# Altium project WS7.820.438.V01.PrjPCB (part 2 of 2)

## Sheet 3-ADC.SchDoc
size A1
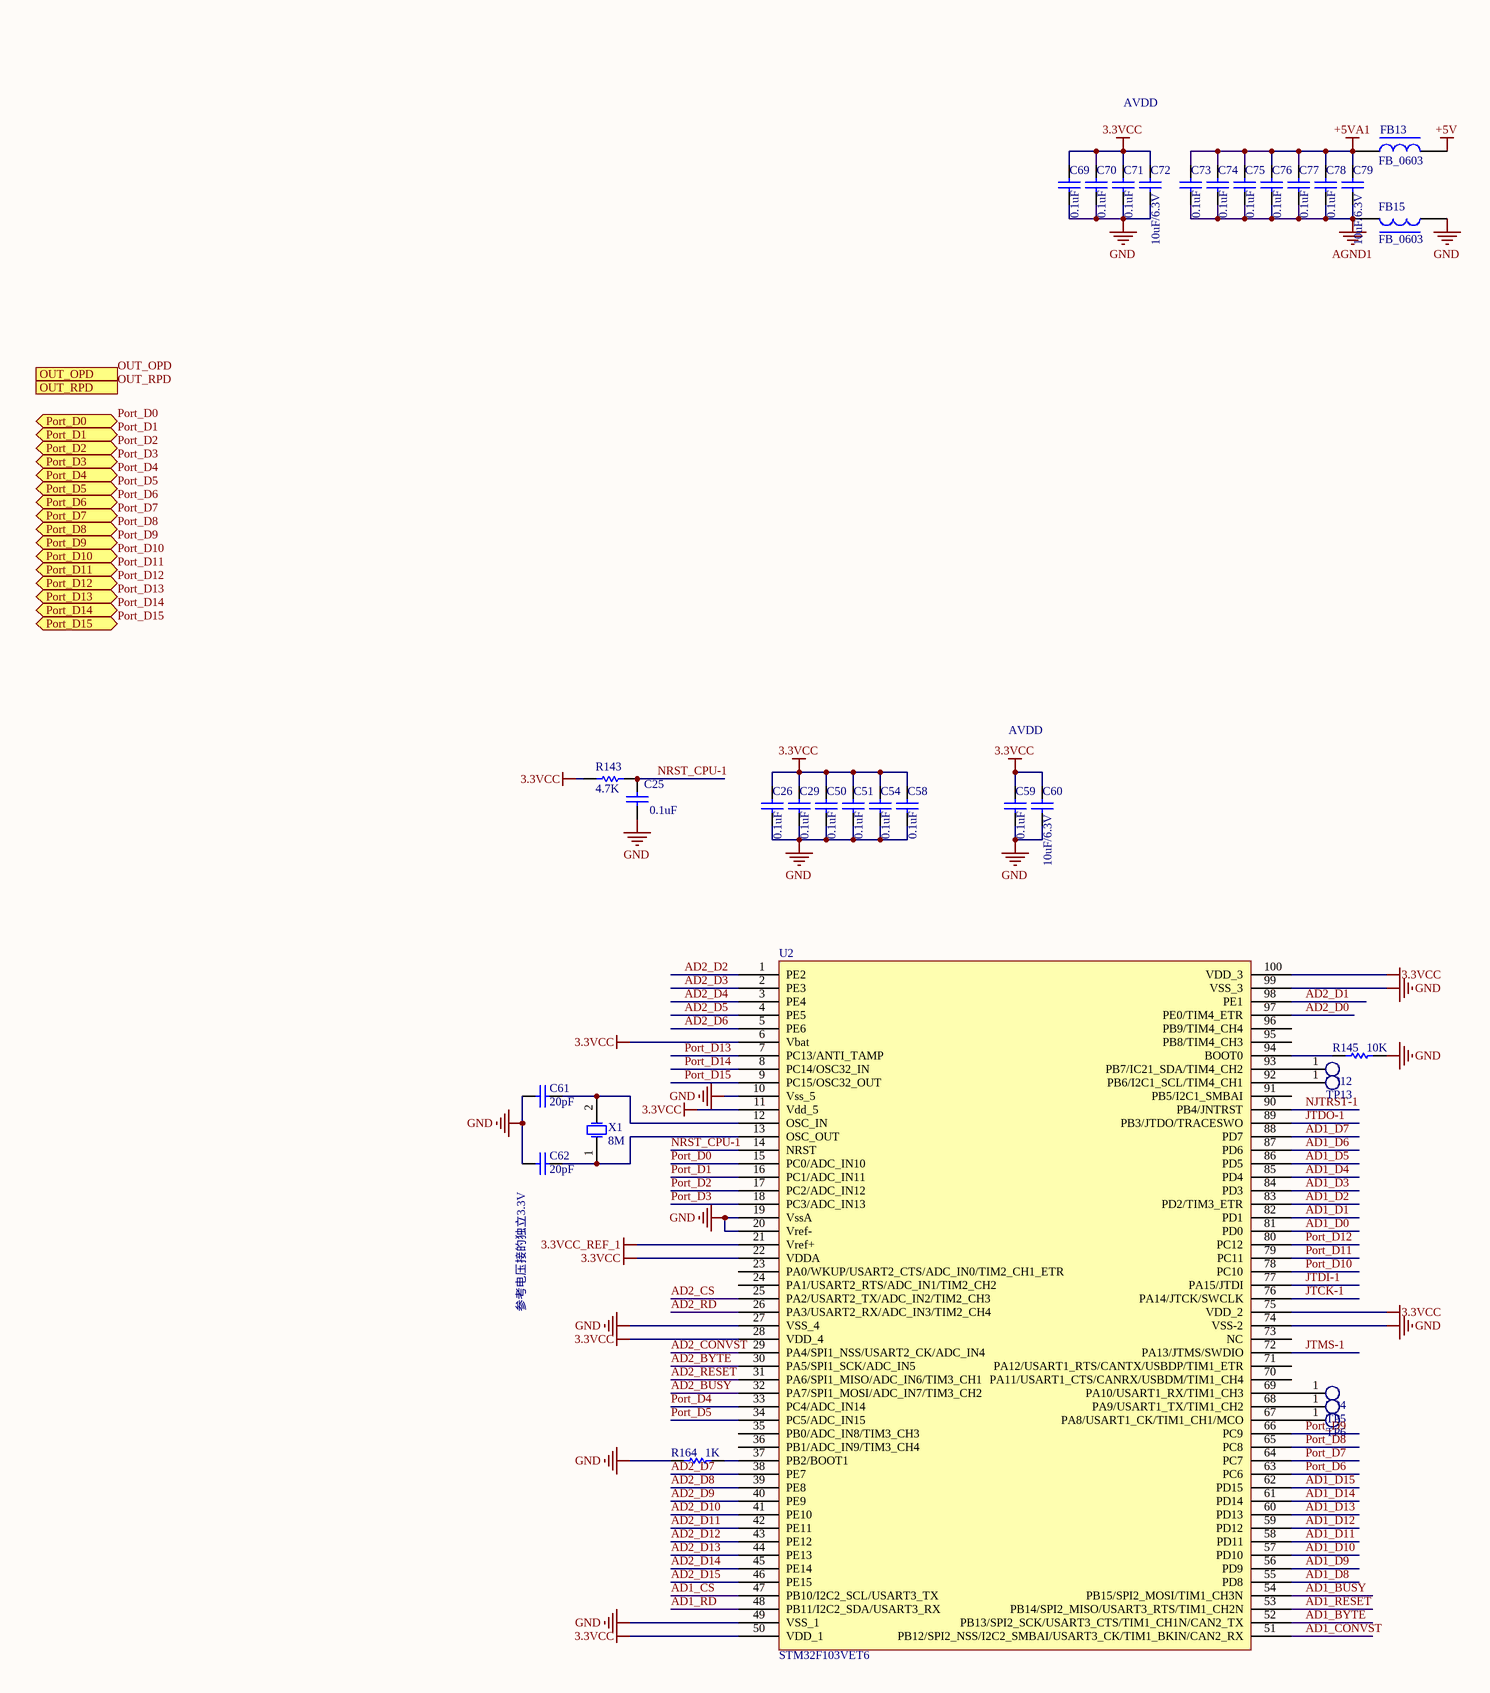
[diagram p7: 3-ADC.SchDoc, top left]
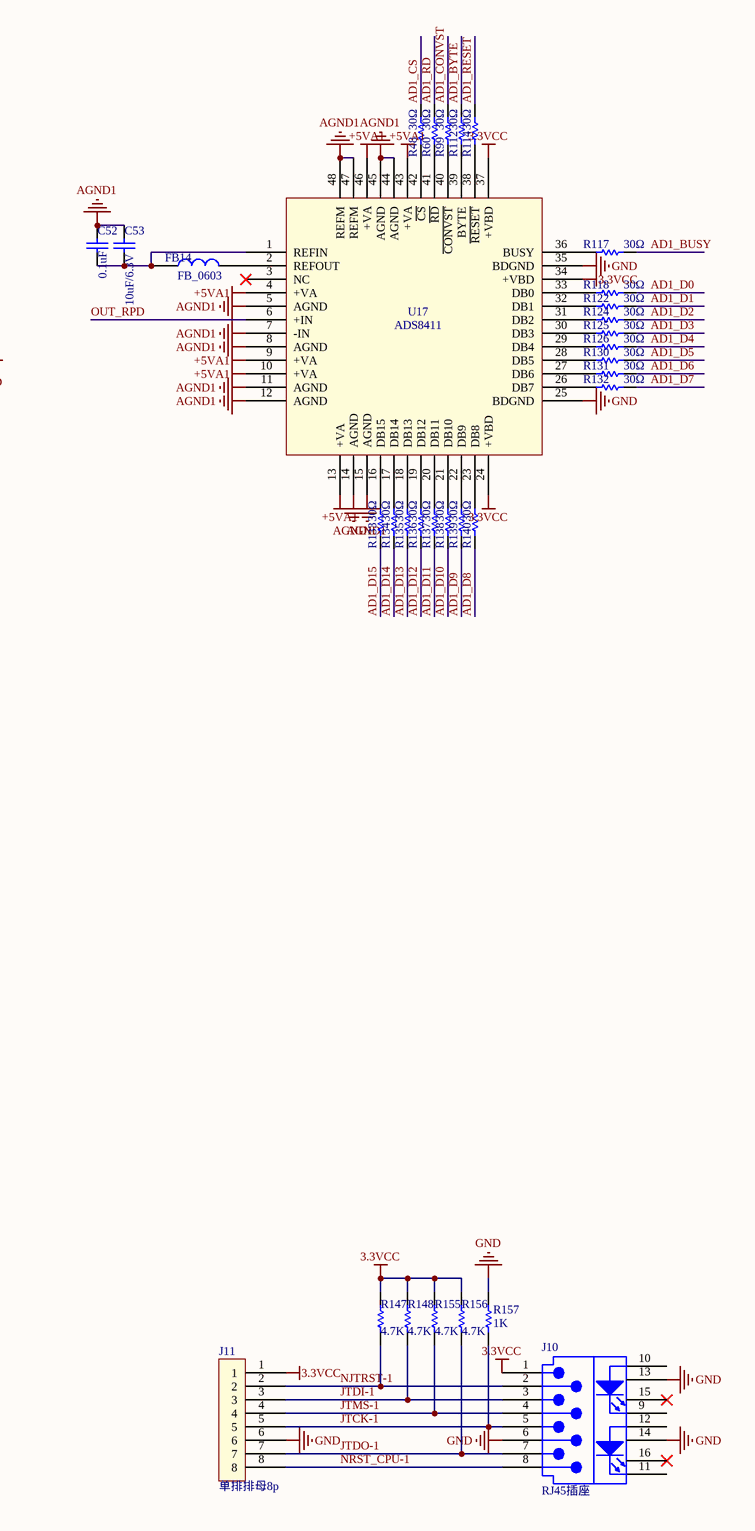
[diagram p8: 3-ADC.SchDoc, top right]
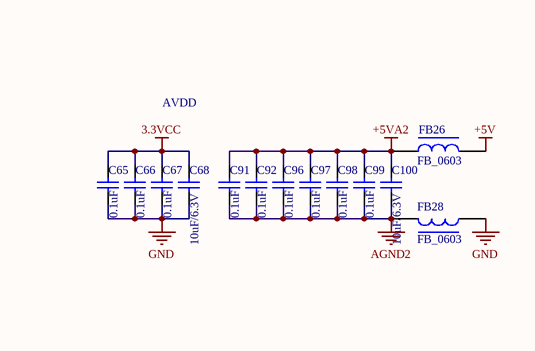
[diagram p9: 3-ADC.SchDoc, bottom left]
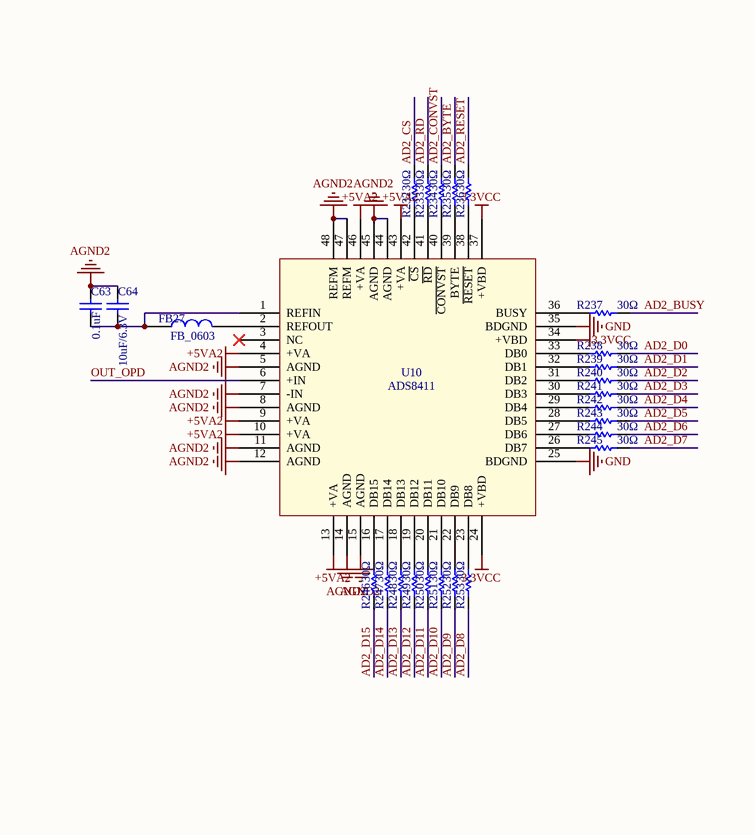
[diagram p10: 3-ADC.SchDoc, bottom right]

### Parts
C25  0.1uF  [C0603]
C26  0.1uF  [C0603]
C29  0.1uF  [C0603]
C50  0.1uF  [C0603]
C51  0.1uF  [C0603]
C52  0.1uF  [C0603]
C53  10uF/6.3V  [C0603]
C54  0.1uF  [C0603]
C58  0.1uF  [C0603]
C59  0.1uF  [C0603]
C60  10uF/6.3V  [C0603]
C61  20pF  [C0603]
C62  20pF  [C0603]
C63  0.1uF  [C0603]
C64  10uF/6.3V  [C0603]
C65  0.1uF  [C0603]
C66  0.1uF  [C0603]
C67  0.1uF  [C0603]
C68  10uF/6.3V  [C0603]
C69  0.1uF  [C0603]
C70  0.1uF  [C0603]
C71  0.1uF  [C0603]
C72  10uF/6.3V  [C0603]
C73  0.1uF  [C0603]
C74  0.1uF  [C0603]
C75  0.1uF  [C0603]
C76  0.1uF  [C0603]
C77  0.1uF  [C0603]
C78  0.1uF  [C0603]
C79  10uF/6.3V  [C0603]
C91  0.1uF  [C0603]
C92  0.1uF  [C0603]
C96  0.1uF  [C0603]
C97  0.1uF  [C0603]
C98  0.1uF  [C0603]
C99  0.1uF  [C0603]
C100  10uF/6.3V  [C0603]
FB13  FB_0603  [L0603]
FB14  FB_0603  [L0603]
FB15  FB_0603  [L0603]
FB26  FB_0603  [L0603]
FB27  FB_0603  [L0603]
FB28  FB_0603  [L0603]
J10  RJ45插座  [RJ45TH-1x1-2R54-LED]
J11  单排排母8p  [SIP8TM-2R54]
R48  30Ω  [R0603]
R60  30Ω  [R0603]
R99  30Ω  [R0603]
R112  30Ω  [R0603]
R114  30Ω  [R0603]
R117  30Ω  [R0603]
R118  30Ω  [R0603]
R122  30Ω  [R0603]
R124  30Ω  [R0603]
R125  30Ω  [R0603]
R126  30Ω  [R0603]
R130  30Ω  [R0603]
R131  30Ω  [R0603]
R132  30Ω  [R0603]
R133  30Ω  [R0603]
R134  30Ω  [R0603]
R135  30Ω  [R0603]
R136  30Ω  [R0603]
R137  30Ω  [R0603]
R138  30Ω  [R0603]
R139  30Ω  [R0603]
R140  30Ω  [R0603]
R143  4.7K  [R0603]
R145  10K  [R0603]
R147  4.7K  [R0603]
R148  4.7K  [R0603]
R155  4.7K  [R0603]
R156  4.7K  [R0603]
R157  1K  [R0603]
R164  1K  [R0603]
R232  30Ω  [R0603]
R233  30Ω  [R0603]
R234  30Ω  [R0603]
R235  30Ω  [R0603]
R236  30Ω  [R0603]
R237  30Ω  [R0603]
R238  30Ω  [R0603]
R239  30Ω  [R0603]
R240  30Ω  [R0603]
R241  30Ω  [R0603]
R242  30Ω  [R0603]
R243  30Ω  [R0603]
R244  30Ω  [R0603]
R245  30Ω  [R0603]
R246  30Ω  [R0603]
R247  30Ω  [R0603]
R248  30Ω  [R0603]
R249  30Ω  [R0603]
R250  30Ω  [R0603]
R251  30Ω  [R0603]
R252  30Ω  [R0603]
R253  30Ω  [R0603]
TP4  TEST  [TP0R8]  (value not drawn)  (no BOM)
TP5  TEST  [TP0R8]  (value not drawn)  (no BOM)
TP6  TEST  [TP0R8]  (value not drawn)  (no BOM)
TP12  TEST  [TP0R8]  (value not drawn)  (no BOM)
TP13  TEST  [TP0R8]  (value not drawn)  (no BOM)
U2  STM32F103VET6  [LQFP100_0R5_14x14]
U10  ADS8411  [TQFN48-0R5-7X7]
U17  ADS8411  [TQFN48-0R5-7X7]
X1  8M  [CRY2SM-6R0x3R5]

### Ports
OUT_OPD (in), OUT_RPD (in), Port_D0 (bidir), Port_D1 (bidir), Port_D2 (bidir), Port_D3 (bidir), Port_D4 (bidir), Port_D5 (bidir), Port_D6 (bidir), Port_D7 (bidir), Port_D8 (bidir), Port_D9 (bidir), Port_D10 (bidir), Port_D11 (bidir), Port_D12 (bidir), Port_D13 (bidir), Port_D14 (bidir), Port_D15 (bidir)

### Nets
3.3VCC: C26.2 C29.2 C50.2 C51.2 C54.2 C58.2 C59.2 C60.2 C65.2 C66.2 C67.2 C68.2 C69.2 C70.2 C71.2 C72.2 J10.1(TX+) J11.1 R143.2 R147.2 R148.2 R155.2 R156.2 U2.6(Vbat) U2.11(Vdd_5) U2.22(VDDA) U2.28(VDD_4) U2.50(VDD_1) U2.75(VDD_2) U2.100(VDD_3) U10.24(+VBD) U10.34(+VBD) U10.37(+VBD) U17.24(+VBD) U17.34(+VBD) U17.37(+VBD)
3.3VCC_REF_1: U2.21(Vref+)
+5V: FB13.2 FB26.2
+5VA1: C73.2 C74.2 C75.2 C76.2 C77.2 C78.2 C79.2 FB13.1 U17.4(+VA) U17.9(+VA) U17.10(+VA) U17.13(+VA) U17.43(+VA) U17.46(+VA)
+5VA2: C91.2 C92.2 C96.2 C97.2 C98.2 C99.2 C100.2 FB26.1 U10.4(+VA) U10.9(+VA) U10.10(+VA) U10.13(+VA) U10.43(+VA) U10.46(+VA)
AGND1: C52.2 C53.2 C73.1 C74.1 C75.1 C76.1 C77.1 C78.1 C79.1 FB15.2 U17.5(AGND) U17.7(-IN) U17.8(AGND) U17.11(AGND) U17.12(AGND) U17.14(AGND) U17.15(AGND) U17.44(AGND) U17.45(AGND) U17.47(REFM) U17.48(REFM)
AGND2: C63.2 C64.2 C91.1 C92.1 C96.1 C97.1 C98.1 C99.1 C100.1 FB28.2 U10.5(AGND) U10.7(-IN) U10.8(AGND) U10.11(AGND) U10.12(AGND) U10.14(AGND) U10.15(AGND) U10.44(AGND) U10.45(AGND) U10.47(REFM) U10.48(REFM)
GND: C25.1 C26.1 C29.1 C50.1 C51.1 C54.1 C58.1 C59.1 C60.1 C61.2 C62.2 C65.1 C66.1 C67.1 C68.1 C69.1 C70.1 C71.1 C72.1 FB15.1 FB28.1 J10.6(RX-) J10.13 J10.14 J11.6 R145.1 R157.1 R164.1 U2.10(Vss_5) U2.19(VssA) U2.20(Vref-) U2.27(VSS_4) U2.49(VSS_1) U2.74(VSS-2) U2.99(VSS_3) U10.25(BDGND) U10.35(BDGND) U17.25(BDGND) U17.35(BDGND)
AD1_BUSY: R117.2 U2.54(PB15/SPI2_MOSI/TIM1_CH3N)
AD1_BYTE: R112.2 U2.52(PB13/SPI2_SCK/USART3_CTS/TIM1_CH1N/CAN2_TX)
AD1_CONVST: R99.2 U2.51(PB12/SPI2_NSS/I2C2_SMBAI/USART3_CK/TIM1_BKIN/CAN2_RX)
AD1_CS: R48.2 U2.47(PB10/I2C2_SCL/USART3_TX)
AD1_D0: R118.2 U2.81(PD0)
AD1_D1: R122.2 U2.82(PD1)
AD1_D2: R124.2 U2.83(PD2/TIM3_ETR)
AD1_D3: R125.2 U2.84(PD3)
AD1_D4: R126.2 U2.85(PD4)
AD1_D5: R130.2 U2.86(PD5)
AD1_D6: R131.2 U2.87(PD6)
AD1_D7: R132.2 U2.88(PD7)
AD1_D8: R140.1 U2.55(PD8)
AD1_D9: R139.1 U2.56(PD9)
AD1_D10: R138.1 U2.57(PD10)
AD1_D11: R137.1 U2.58(PD11)
AD1_D12: R136.1 U2.59(PD12)
AD1_D13: R135.1 U2.60(PD13)
AD1_D14: R134.1 U2.61(PD14)
AD1_D15: R133.1 U2.62(PD15)
AD1_RD: R60.2 U2.48(PB11/I2C2_SDA/USART3_RX)
AD1_RESET: R114.2 U2.53(PB14/SPI2_MISO/USART3_RTS/TIM1_CH2N)
AD2_BUSY: R237.2 U2.32(PA7/SPI1_MOSI/ADC_IN7/TIM3_CH2)
AD2_BYTE: R235.2 U2.30(PA5/SPI1_SCK/ADC_IN5)
AD2_CONVST: R234.2 U2.29(PA4/SPI1_NSS/USART2_CK/ADC_IN4)
AD2_CS: R232.2 U2.25(PA2/USART2_TX/ADC_IN2/TIM2_CH3)
AD2_D0: R238.2 U2.97(PE0/TIM4_ETR)
AD2_D1: R239.2 U2.98(PE1)
AD2_D2: R240.2 U2.1(PE2)
AD2_D3: R241.2 U2.2(PE3)
AD2_D4: R242.2 U2.3(PE4)
AD2_D5: R243.2 U2.4(PE5)
AD2_D6: R244.2 U2.5(PE6)
AD2_D7: R245.2 U2.38(PE7)
AD2_D8: R253.1 U2.39(PE8)
AD2_D9: R252.1 U2.40(PE9)
AD2_D10: R251.1 U2.41(PE10)
AD2_D11: R250.1 U2.42(PE11)
AD2_D12: R249.1 U2.43(PE12)
AD2_D13: R248.1 U2.44(PE13)
AD2_D14: R247.1 U2.45(PE14)
AD2_D15: R246.1 U2.46(PE15)
AD2_RD: R233.2 U2.26(PA3/USART2_RX/ADC_IN3/TIM2_CH4)
AD2_RESET: R236.2 U2.31(PA6/SPI1_MISO/ADC_IN6/TIM3_CH1)
JTCK-1: J10.5(NC) J11.5 R157.2 U2.76(PA14/JTCK/SWCLK)
JTDI-1: J10.3(RX+) J11.3 R148.1 U2.77(PA15/JTDI)
JTDO-1: J10.7(NC) J11.7 R156.1 U2.89(PB3/JTDO/TRACESWO)
JTMS-1: J10.4(NC) J11.4 R155.1 U2.72(PA13/JTMS/SWDIO)
NJTRST-1: J10.2(TX-) J11.2 R147.1 U2.90(PB4/JNTRST)
NRST_CPU-1: C25.2 J10.8(NC) J11.8 R143.1 U2.14(NRST)
OUT_OPD: U10.6(+IN) ; port OUT_OPD
OUT_RPD: U17.6(+IN) ; port OUT_RPD
Port_D0: U2.15(PC0/ADC_IN10) ; port Port_D0
Port_D1: U2.16(PC1/ADC_IN11) ; port Port_D1
Port_D2: U2.17(PC2/ADC_IN12) ; port Port_D2
Port_D3: U2.18(PC3/ADC_IN13) ; port Port_D3
Port_D4: U2.33(PC4/ADC_IN14) ; port Port_D4
Port_D5: U2.34(PC5/ADC_IN15) ; port Port_D5
Port_D6: U2.63(PC6) ; port Port_D6
Port_D7: U2.64(PC7) ; port Port_D7
Port_D8: U2.65(PC8) ; port Port_D8
Port_D9: U2.66(PC9) ; port Port_D9
Port_D10: U2.78(PC10) ; port Port_D10
Port_D11: U2.79(PC11) ; port Port_D11
Port_D12: U2.80(PC12) ; port Port_D12
Port_D13: U2.7(PC13/ANTI_TAMP) ; port Port_D13
Port_D14: U2.8(PC14/OSC32_IN) ; port Port_D14
Port_D15: U2.9(PC15/OSC32_OUT) ; port Port_D15
NetC52_1: C52.1 C53.1 FB14.1 U17.1(REFIN)
NetC61_1: C61.1 U2.12(OSC_IN) X1.2(OSC2)
NetC62_1: C62.1 U2.13(OSC_OUT) X1.1(OSC1)
NetC63_1: C63.1 C64.1 FB27.1 U10.1(REFIN)
NetFB14_2: FB14.2 U17.2(REFOUT)
NetFB27_2: FB27.2 U10.2(REFOUT)
NetR48_1: R48.1 U17.42(~{CS})
NetR60_1: R60.1 U17.41(~{RD})
NetR99_1: R99.1 U17.40(~{CONVST})
NetR112_1: R112.1 U17.39(BYTE)
NetR114_1: R114.1 U17.38(~{RESET})
NetR117_1: R117.1 U17.36(BUSY)
NetR118_1: R118.1 U17.33(DB0)
NetR122_1: R122.1 U17.32(DB1)
NetR124_1: R124.1 U17.31(DB2)
NetR125_1: R125.1 U17.30(DB3)
NetR126_1: R126.1 U17.29(DB4)
NetR130_1: R130.1 U17.28(DB5)
NetR131_1: R131.1 U17.27(DB6)
NetR132_1: R132.1 U17.26(DB7)
NetR133_2: R133.2 U17.16(DB15)
NetR134_2: R134.2 U17.17(DB14)
NetR135_2: R135.2 U17.18(DB13)
NetR136_2: R136.2 U17.19(DB12)
NetR137_2: R137.2 U17.20(DB11)
NetR138_2: R138.2 U17.21(DB10)
NetR139_2: R139.2 U17.22(DB9)
NetR140_2: R140.2 U17.23(DB8)
NetR145_2: R145.2 U2.94(BOOT0)
NetR164_2: R164.2 U2.37(PB2/BOOT1)
NetR232_1: R232.1 U10.42(~{CS})
NetR233_1: R233.1 U10.41(~{RD})
NetR234_1: R234.1 U10.40(~{CONVST})
NetR235_1: R235.1 U10.39(BYTE)
NetR236_1: R236.1 U10.38(~{RESET})
NetR237_1: R237.1 U10.36(BUSY)
NetR238_1: R238.1 U10.33(DB0)
NetR239_1: R239.1 U10.32(DB1)
NetR240_1: R240.1 U10.31(DB2)
NetR241_1: R241.1 U10.30(DB3)
NetR242_1: R242.1 U10.29(DB4)
NetR243_1: R243.1 U10.28(DB5)
NetR244_1: R244.1 U10.27(DB6)
NetR245_1: R245.1 U10.26(DB7)
NetR246_2: R246.2 U10.16(DB15)
NetR247_2: R247.2 U10.17(DB14)
NetR248_2: R248.2 U10.18(DB13)
NetR249_2: R249.2 U10.19(DB12)
NetR250_2: R250.2 U10.20(DB11)
NetR251_2: R251.2 U10.21(DB10)
NetR252_2: R252.2 U10.22(DB9)
NetR253_2: R253.2 U10.23(DB8)
NetTP4_1: TP4.1(TP) U2.69(PA10/USART1_RX/TIM1_CH3)
NetTP5_1: TP5.1(TP) U2.68(PA9/USART1_TX/TIM1_CH2)
NetTP6_1: TP6.1(TP) U2.67(PA8/USART1_CK/TIM1_CH1/MCO)
NetTP12_1: TP12.1(TP) U2.93(PB7/IC21_SDA/TIM4_CH2)
NetTP13_1: TP13.1(TP) U2.92(PB6/I2C1_SCL/TIM4_CH1)

Not connected (* = marked no-connect by the designer): J10 9(K1) 10(A1) 11(K2) 12(A2) 15* 16*; U2 23(PA0/WKUP/USART2_CTS/ADC_IN0/TIM2_CH1_ETR) 24(PA1/USART2_RTS/ADC_IN1/TIM2_CH2) 35(PB0/ADC_IN8/TIM3_CH3) 36(PB1/ADC_IN9/TIM3_CH4) 70(PA11/USART1_CTS/CANRX/USBDM/TIM1_CH4) 71(PA12/USART1_RTS/CANTX/USBDP/TIM1_ETR) 73(NC) 91(PB5/I2C1_SMBAI) 95(PB8/TIM4_CH3) 96(PB9/TIM4_CH4); U10 3(NC)*; U17 3(NC)*

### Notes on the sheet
- AVDD
- 参考电压接的独立3.3V

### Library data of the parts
C25 C26 C29 C50-C52 C54 C58 C59 C63 C65-C67 C69-C71 C73-C78 C91 C92 C96-C99 = 0.1uF贴片电容: 贴片电容_GRM188R71H104KA01D_0.1uF±10%,50V,0603; code: 01010045
C53 C60 C64 C68 C72 C79 C100 = 10uF贴片电容: 贴片电容_GRM188R60J106ME47D_10uF±20%,6.3V,0603; code: 01010037
C61 C62 = 20pF贴片电容: 贴片电容_GRM188C1H200JB01D_20pF±5%,50V,0603; code: 01010035
FB13-FB15 FB26-FB28 = 0603贴片磁珠: 贴片磁珠_100R,0603; code: 0103016
J10 = RJ45弯脚带灯: RJ45插座_1*1,带左黄右绿灯,弯脚; MPN: 朱迅; code: 01090042
J11 = 8p-2.54单排母座: 连接器_单排排母座8p_直插,间距2.54mm; MPN: WS; code: 01090052
R48 R60 R99 R112 R114 R117 R118 R122 R124-R126 R130-R140 R232-R253 = 30Ω贴片电阻: 贴片电阻_30Ω±5%,0603; code: 01020108
R143 R147 R148 R155 R156 = 4.7K贴片电阻: 贴片电阻_4.7K±5%,0603; code: 01020012
R145 = 10K贴片电阻: 贴片电阻_10K±5%,0603; code: 01020011
R157 R164 = 1K贴片电阻: 贴片电阻_1K±5%,0603; code: 01020082
TP4-TP6 TP12 TP13 = TP0.8mm: 表贴测试点0.8mm
U2 = STM32F103VET: MCU_STM32F103VET6_32 bit, LQFP100; Maker: ST; code: 01060037
U10 U17 = ADS8411: 模数转换芯片_ADS8411_16-Bit,2MSPS,QFN48
X1 = 8M贴片无源晶体: 贴片无源晶体_8MHz,封装6035; code: 03050006

## Sheet 4-RF-PD.SchDoc
size A2
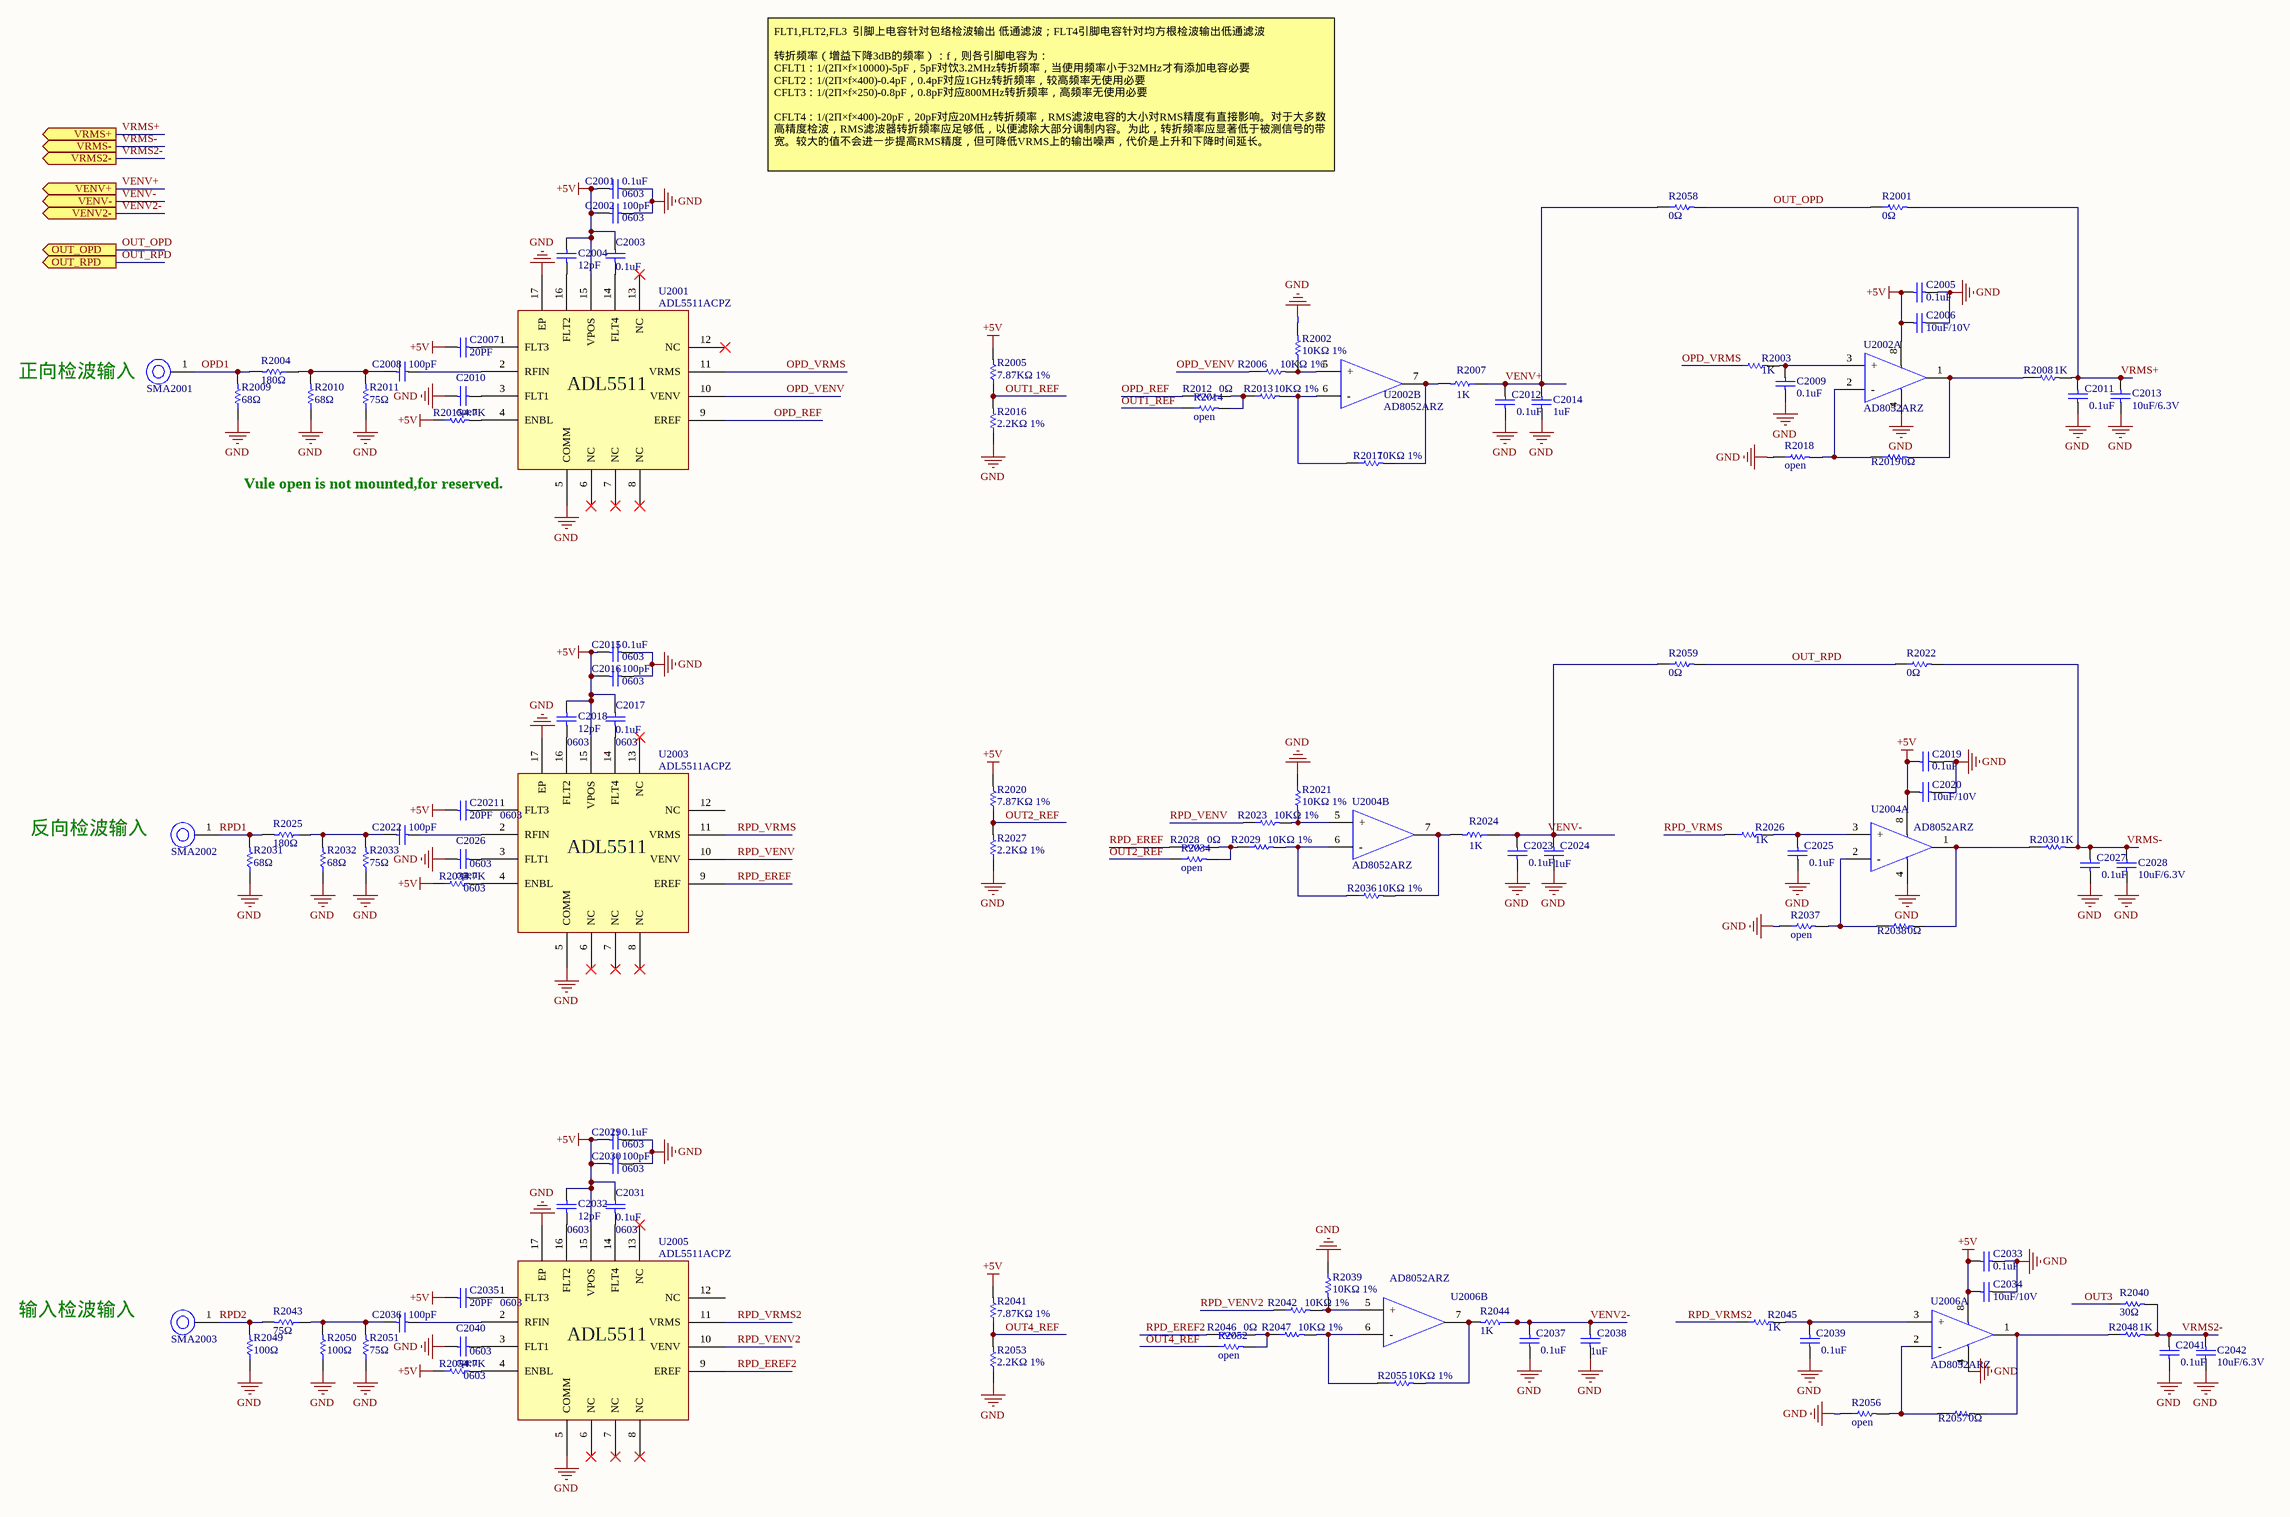
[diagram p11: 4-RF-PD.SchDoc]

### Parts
C2001  0.1uF  [C0603]
C2002  100pF  [C0603]
C2003  0.1uF  [C0603]
C2004  12pF  [C0603]
C2005  0.1uF  [C0603]
C2006  10uF/10V  [C0805]
C2007  20PF  [C0603]
C2008  100pF  [C0805]
C2009  0.1uF  [C0603]
C2010  open  [C0603]  (no BOM)
C2011  0.1uF  [C0603]
C2012  0.1uF  [C0603]
C2013  10uF/6.3V  [C0603]
C2014  1uF  [C0603]
C2015  0.1uF  [C0603]
C2016  100pF  [C0603]
C2017  0.1uF  [C0603]
C2018  12pF  [C0603]
C2019  0.1uF  [C0603]
C2020  10uF/10V  [C0805]
C2021  20PF  [C0603]
C2022  100pF  [C0805]
C2023  0.1uF  [C0603]
C2024  1uF  [C0603]
C2025  0.1uF  [C0603]
C2026  open  [C0603]  (no BOM)
C2027  0.1uF  [C0603]
C2028  10uF/6.3V  [C0603]
C2029  0.1uF  [C0603]
C2030  100pF  [C0603]
C2031  0.1uF  [C0603]
C2032  12pF  [C0603]
C2033  0.1uF  [C0603]
C2034  10uF/10V  [C0805]
C2035  20PF  [C0603]
C2036  100pF  [C0805]
C2037  0.1uF  [C0603]
C2038  1uF  [C0603]
C2039  0.1uF  [C0603]
C2040  open  [C0603]  (no BOM)
C2041  0.1uF  [C0603]
C2042  10uF/6.3V  [C0603]
R2001  0Ω  [R0603]  (no BOM)
R2002  10KΩ 1%  [R0603]
R2003  1K  [R0603]
R2004  180Ω  [R1206]
R2005  7.87KΩ 1%  [R0603]
R2006  10KΩ 1%  [R0603]
R2007  1K  [R0603]
R2008  1K  [R0603]
R2009  68Ω  [R1206]
R2010  68Ω  [R1206]
R2011  75Ω  [R0805]
R2012  0Ω  [R0603]
R2013  10KΩ 1%  [R0603]
R2014  open  [R0603]  (no BOM)
R2015  4.7K  [R0603]
R2016  2.2KΩ 1%  [R0603]
R2017  10KΩ 1%  [R0603]
R2018  open  [R0603]  (no BOM)
R2019  0Ω  [R0603]
R2020  7.87KΩ 1%  [R0603]
R2021  10KΩ 1%  [R0603]
R2022  0Ω  [R0603]  (no BOM)
R2023  10KΩ 1%  [R0603]
R2024  1K  [R0603]
R2025  180Ω  [R1206]
R2026  1K  [R0603]
R2027  2.2KΩ 1%  [R0603]
R2028  0Ω  [R0603]
R2029  10KΩ 1%  [R0603]
R2030  1K  [R0603]
R2031  68Ω  [R1206]
R2032  68Ω  [R1206]
R2033  75Ω  [R0805]
R2034  open  [R0603]  (no BOM)
R2035  4.7K  [R0603]
R2036  10KΩ 1%  [R0603]
R2037  open  [R0603]  (no BOM)
R2038  0Ω  [R0603]
R2039  10KΩ 1%  [R0603]
R2040  30Ω  [R0603]
R2041  7.87KΩ 1%  [R0603]
R2042  10KΩ 1%  [R0603]
R2043  75Ω  [R1206]
R2044  1K  [R0603]
R2045  1K  [R0603]
R2046  0Ω  [R0603]
R2047  10KΩ 1%  [R0603]
R2048  1K  [R0603]
R2049  100Ω  [R1206]
R2050  100Ω  [R1206]
R2051  75Ω  [R0805]
R2052  open  [R0603]  (no BOM)
R2053  2.2KΩ 1%  [R0603]
R2054  4.7K  [R0603]
R2055  10KΩ 1%  [R0603]
R2056  open  [R0603]  (no BOM)
R2057  0Ω  [R0603]
R2058  0Ω  [R0603]
R2059  0Ω  [R0603]
SMA2001  SMA-50KFD-4  [SMA-50KFD-4]  (value not drawn)  (no BOM)
SMA2002  SMA-50KFD-4  [SMA-50KFD-4]  (value not drawn)  (no BOM)
SMA2003  SMA-50KFD-4  [SMA-50KFD-4]  (value not drawn)  (no BOM)
U2001  ADL5511ACPZ  [QFN16_0R50_3X3]
U2002  AD8052ARZ  [SOIC8_1R27_3R9x4R9]  (parts A,B of 2)
U2003  ADL5511ACPZ  [QFN16_0R50_3X3]
U2004  AD8052ARZ  [SOIC8_1R27_3R9x4R9]  (parts A,B of 2)
U2005  ADL5511ACPZ  [QFN16_0R50_3X3]
U2006  AD8052ARZ  [SOIC8_1R27_3R9x4R9]  (parts A,B of 2)

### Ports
OUT_OPD (out), OUT_RPD (out), VENV2- (out), VENV+ (out), VENV- (out), VRMS2- (out), VRMS+ (out), VRMS- (out)

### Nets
+5V: C2001.2 C2002.1 C2003.2 C2004.2 C2005.1 C2006.1 C2007.1 C2015.2 C2016.1 C2017.2 C2018.2 C2019.1 C2020.1 C2021.1 C2029.2 C2030.1 C2031.2 C2032.2 C2033.1 C2034.1 C2035.1 R2005.2 R2015.1 R2020.2 R2035.1 R2041.2 R2054.1 U2001.15(VPOS) U2002.8 U2003.15(VPOS) U2004.8 U2005.15(VPOS) U2006.8
GND: C2001.1 C2002.2 C2005.2 C2006.2 C2009.1 C2010.1 C2011.1 C2012.1 C2013.1 C2014.1 C2015.1 C2016.2 C2019.2 C2020.2 C2023.1 C2024.1 C2025.1 C2026.1 C2027.1 C2028.1 C2029.1 C2030.2 C2033.2 C2034.2 C2037.1 C2038.1 C2039.1 C2040.1 C2041.1 C2042.1 R2002.2 R2009.1 R2010.1 R2011.1 R2016.1 R2018.1 R2021.1 R2027.1 R2031.1 R2032.1 R2033.1 R2037.1 R2039.1 R2049.1 R2050.1 R2051.1 R2053.1 R2056.1 U2001.5(COMM) U2001.17(EP) U2002.4 U2003.5(COMM) U2003.17(EP) U2004.4 U2005.5(COMM) U2005.17(EP) U2006.4
OPD1: R2004.2 R2009.2 SMA2001.1(Sig)
OPD_REF: R2012.1 U2001.9(EREF)
OPD_VENV: R2006.1 U2001.10(VENV)
OPD_VRMS: R2003.1 U2001.11(VRMS)
OUT1_REF: R2005.1 R2014.1 R2016.2
OUT2_REF: R2020.1 R2027.2 R2034.1
OUT3: R2040.1
OUT4_REF: R2041.1 R2052.1 R2053.2
OUT_OPD: R2001.1 R2058.2 ; port OUT_OPD
OUT_RPD: R2022.1 R2059.2 ; port OUT_RPD
RPD1: R2025.2 R2031.2 SMA2002.1(Sig)
RPD2: R2043.2 R2049.2 SMA2003.1(Sig)
RPD_EREF: R2028.1 U2003.9(EREF)
RPD_EREF2: R2046.1 U2005.9(EREF)
RPD_VENV: R2023.1 U2003.10(VENV)
RPD_VENV2: R2042.1 U2005.10(VENV)
RPD_VRMS: R2026.1 U2003.11(VRMS)
RPD_VRMS2: R2045.1 U2005.11(VRMS)
VENV2-: C2037.2 C2038.2 R2044.1 ; port VENV2-
VENV+: C2012.2 C2014.2 R2007.1 R2058.1 ; port VENV+
VENV-: C2023.2 C2024.2 R2024.1 R2059.1 ; port VENV-
VRMS2-: C2041.2 C2042.2 R2040.2 R2048.2 ; port VRMS2-
VRMS+: C2011.2 C2013.2 R2001.2 R2008.2 ; port VRMS+
VRMS-: C2027.2 C2028.2 R2022.2 R2030.2 ; port VRMS-
NetC2003_1: C2003.1 U2001.14(FLT4)
NetC2004_1: C2004.1 U2001.16(FLT2)
NetC2007_2: C2007.2 U2001.1(FLT3)
NetC2008_1: C2008.1 R2004.1 R2010.2 R2011.2
NetC2008_2: C2008.2 U2001.2(RFIN)
NetC2009_2: C2009.2 R2003.2 U2002.3(+)
NetC2010_2: C2010.2 U2001.3(FLT1)
NetC2017_1: C2017.1 U2003.14(FLT4)
NetC2018_1: C2018.1 U2003.16(FLT2)
NetC2021_2: C2021.2 U2003.1(FLT3)
NetC2022_1: C2022.1 R2025.1 R2032.2 R2033.2
NetC2022_2: C2022.2 U2003.2(RFIN)
NetC2025_2: C2025.2 R2026.2 U2004.3(+)
NetC2026_2: C2026.2 U2003.3(FLT1)
NetC2031_1: C2031.1 U2005.14(FLT4)
NetC2032_1: C2032.1 U2005.16(FLT2)
NetC2035_2: C2035.2 U2005.1(FLT3)
NetC2036_1: C2036.1 R2043.1 R2050.2 R2051.2
NetC2036_2: C2036.2 U2005.2(RFIN)
NetC2039_2: C2039.2 R2045.2 U2006.3(+)
NetC2040_2: C2040.2 U2005.3(FLT1)
NetR2002_1: R2002.1 R2006.2 U2002.5(+)
NetR2007_2: R2007.2 R2017.2 U2002.7
NetR2008_1: R2008.1 R2019.2 U2002.1
NetR2012_2: R2012.2 R2013.1 R2014.2
NetR2013_2: R2013.2 R2017.1 U2002.6(-)
NetR2015_2: R2015.2 U2001.4(ENBL)
NetR2018_2: R2018.2 R2019.1 U2002.2(-)
NetR2021_2: R2021.2 R2023.2 U2004.5(+)
NetR2024_2: R2024.2 R2036.2 U2004.7
NetR2028_2: R2028.2 R2029.1 R2034.2
NetR2029_2: R2029.2 R2036.1 U2004.6(-)
NetR2030_1: R2030.1 R2038.2 U2004.1
NetR2035_2: R2035.2 U2003.4(ENBL)
NetR2037_2: R2037.2 R2038.1 U2004.2(-)
NetR2039_2: R2039.2 R2042.2 U2006.5(+)
NetR2044_2: R2044.2 R2055.2 U2006.7
NetR2046_2: R2046.2 R2047.1 R2052.2
NetR2047_2: R2047.2 R2055.1 U2006.6(-)
NetR2048_1: R2048.1 R2057.2 U2006.1
NetR2054_2: R2054.2 U2005.4(ENBL)
NetR2056_2: R2056.2 R2057.1 U2006.2(-)

Not connected (* = marked no-connect by the designer): U2001 6(NC)* 7(NC)* 8(NC)* 12(NC)* 13(NC)*; U2003 6(NC)* 7(NC)* 8(NC)* 12(NC) 13(NC)*; U2005 6(NC)* 7(NC)* 8(NC)* 12(NC) 13(NC)*

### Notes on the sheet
- FLT1,FLT2,FL3  引脚上电容针对包络检波输出 低通滤波；FLT4引脚电容针对均方根检波输出低通滤波
  转折频率（增益下降3dB的频率）：f，则各引脚电容为：
  CFLT1：1/(2Π×f×10000)-5pF，5pF对饮3.2MHz转折频率，当使用频率小于32MHz才有添加电容必要
  CFLT2：1/(2Π×f×400)-0.4pF，0.4pF对应1GHz转折频率，较高频率无使用必要
  CFLT3：1/(2Π×f×250)-0.8pF，0.8pF对应800MHz转折频率，高频率无使用必要
  CFLT4：1/(2Π×f×400)-20pF，20pF对应20MHz转折频率，RMS滤波电容的大小对RMS精度有直接影响。对于大多数高精度检波，RMS滤波器转折频率应足够低，以便滤除大部分调制内容。为此，转折频率应显著低于被测信号的带宽。较大的值不会进一步提高RMS精度，但可降低VRMS上的输出噪声，代价是上升和下降时间延长。
- (near C2002) 0603
- (near C2001) 0603
- 正向检波输入
- (near U2001) Vule open is not mounted,for reserved.
- (near C2015) 0603
- (near C2016) 0603
- (near C2018) 0603
- (near C2017) 0603
- 反向检波输入
- (near U2003) 0603
- (near R2035) 0603
- (near C2026) 0603
- (near C2029) 0603
- (near C2030) 0603
- (near C2032) 0603
- (near C2031) 0603
- 输入检波输入
- (near U2005) 0603
- (near R2054) 0603
- (near C2040) 0603

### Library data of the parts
C2001 C2003 C2005 C2009 C2011 C2012 C2015 C2017 C2019 C2023 C2025 C2027 C2029 C2031 C2033 C2037 C2039 C2041 = 0.1uF贴片电容: as C25 on sheet 3-ADC
C2002 C2016 C2030 = 1000pF贴片电容: 贴片电容_100pF±10%,50V,0603
C2004 C2018 C2032 = 10pF贴片电容: GRM1885C1H390JA01D_39pF±5%,50V,0603; code: 01010157
C2006 C2020 C2034 = 10uF贴片电容: 贴片电容_GRM21BR61A106KE19L_10uF±10%,10V,0805; code: 01010036
C2007 C2021 C2035 = 10pF贴片电容: 贴片电容_GRM1885C1H680JA01D_0603,68PF,50V,±5％,COG; MPN: Murata; code: 01010034
C2008 C2022 C2036 = 100pF贴片电容: 贴片电容_GRM2165C1H101JA01D_100pF±5%,50V,0805; code: 01010043
C2010 C2026 C2040 = 1000pF贴片电容: 贴片电容_GRM188R71H102KA01_1000pF±10%,50V,0603; code: 01010093
C2013 C2028 C2042 = 10uF贴片电容: as C53 on sheet 3-ADC
C2014 C2024 C2038 = 10uF贴片电容: code: 01010037
R2001 R2007 R2022 R2024 R2040 R2044 R2058 R2059 = 0Ω贴片电阻: code: 01020010
R2002 R2006 R2013 R2017 R2021 R2023 R2029 R2036 R2039 R2042 R2047 R2055 = 430Ω贴片电阻: code: 01020118
R2003 R2026 R2045 = 1K贴片电阻: 贴片电阻_1K±5%,0603; code: 01020082
R2004 R2025 = 56Ω贴片电阻: 贴片电阻_1206,180Ω,±5％
R2005 R2020 R2041 = 0Ω贴片电阻: 0603,7.87KΩ,±1％; code: 01020010
R2008 R2012 R2014 R2019 R2028 R2030 R2034 R2038 R2046 R2048 R2052 R2057 = 0Ω贴片电阻: 贴片电阻_0Ω±5%,0603; code: 01020010
R2009 R2010 R2031 R2032 = 56Ω贴片电阻: 贴片电阻_68Ω±5%,1206
R2011 R2033 R2051 = 75Ω贴片电阻: 贴片电阻_75Ω±5%,0805; code: 01020068
R2015 R2035 R2054 = 4.7K贴片电阻: 贴片电阻_4.7K±5%,0603; code: 01020012
R2016 R2027 R2053 = 0Ω贴片电阻: 0603,2.2KΩ,±1％; code: 01020010
R2018 R2037 R2056 = 0Ω贴片电阻
R2043 = 56Ω贴片电阻: 贴片电阻_75Ω±5%,1206
R2049 R2050 = 56Ω贴片电阻: 贴片电阻_100Ω±5%,1206
SMA2001-SMA2003 = SMA-50KFD-4: 射频同轴连接器_SMA-50KFD-4; code: 03100009
U2001 U2003 U2005 = ADL5511ACPZ: 检波器_ADL5511ACPZ_DC~6GHz,LFCSP16; code: 01060108
U2002 U2006 = OP284: Maker: TI; code: 01060201
U2004 = LM358: 运算放大器_LM358_SOIC8; Maker: MOTOROLA; code: 01060025

## Sheet 5-POWER.SchDoc
size A3
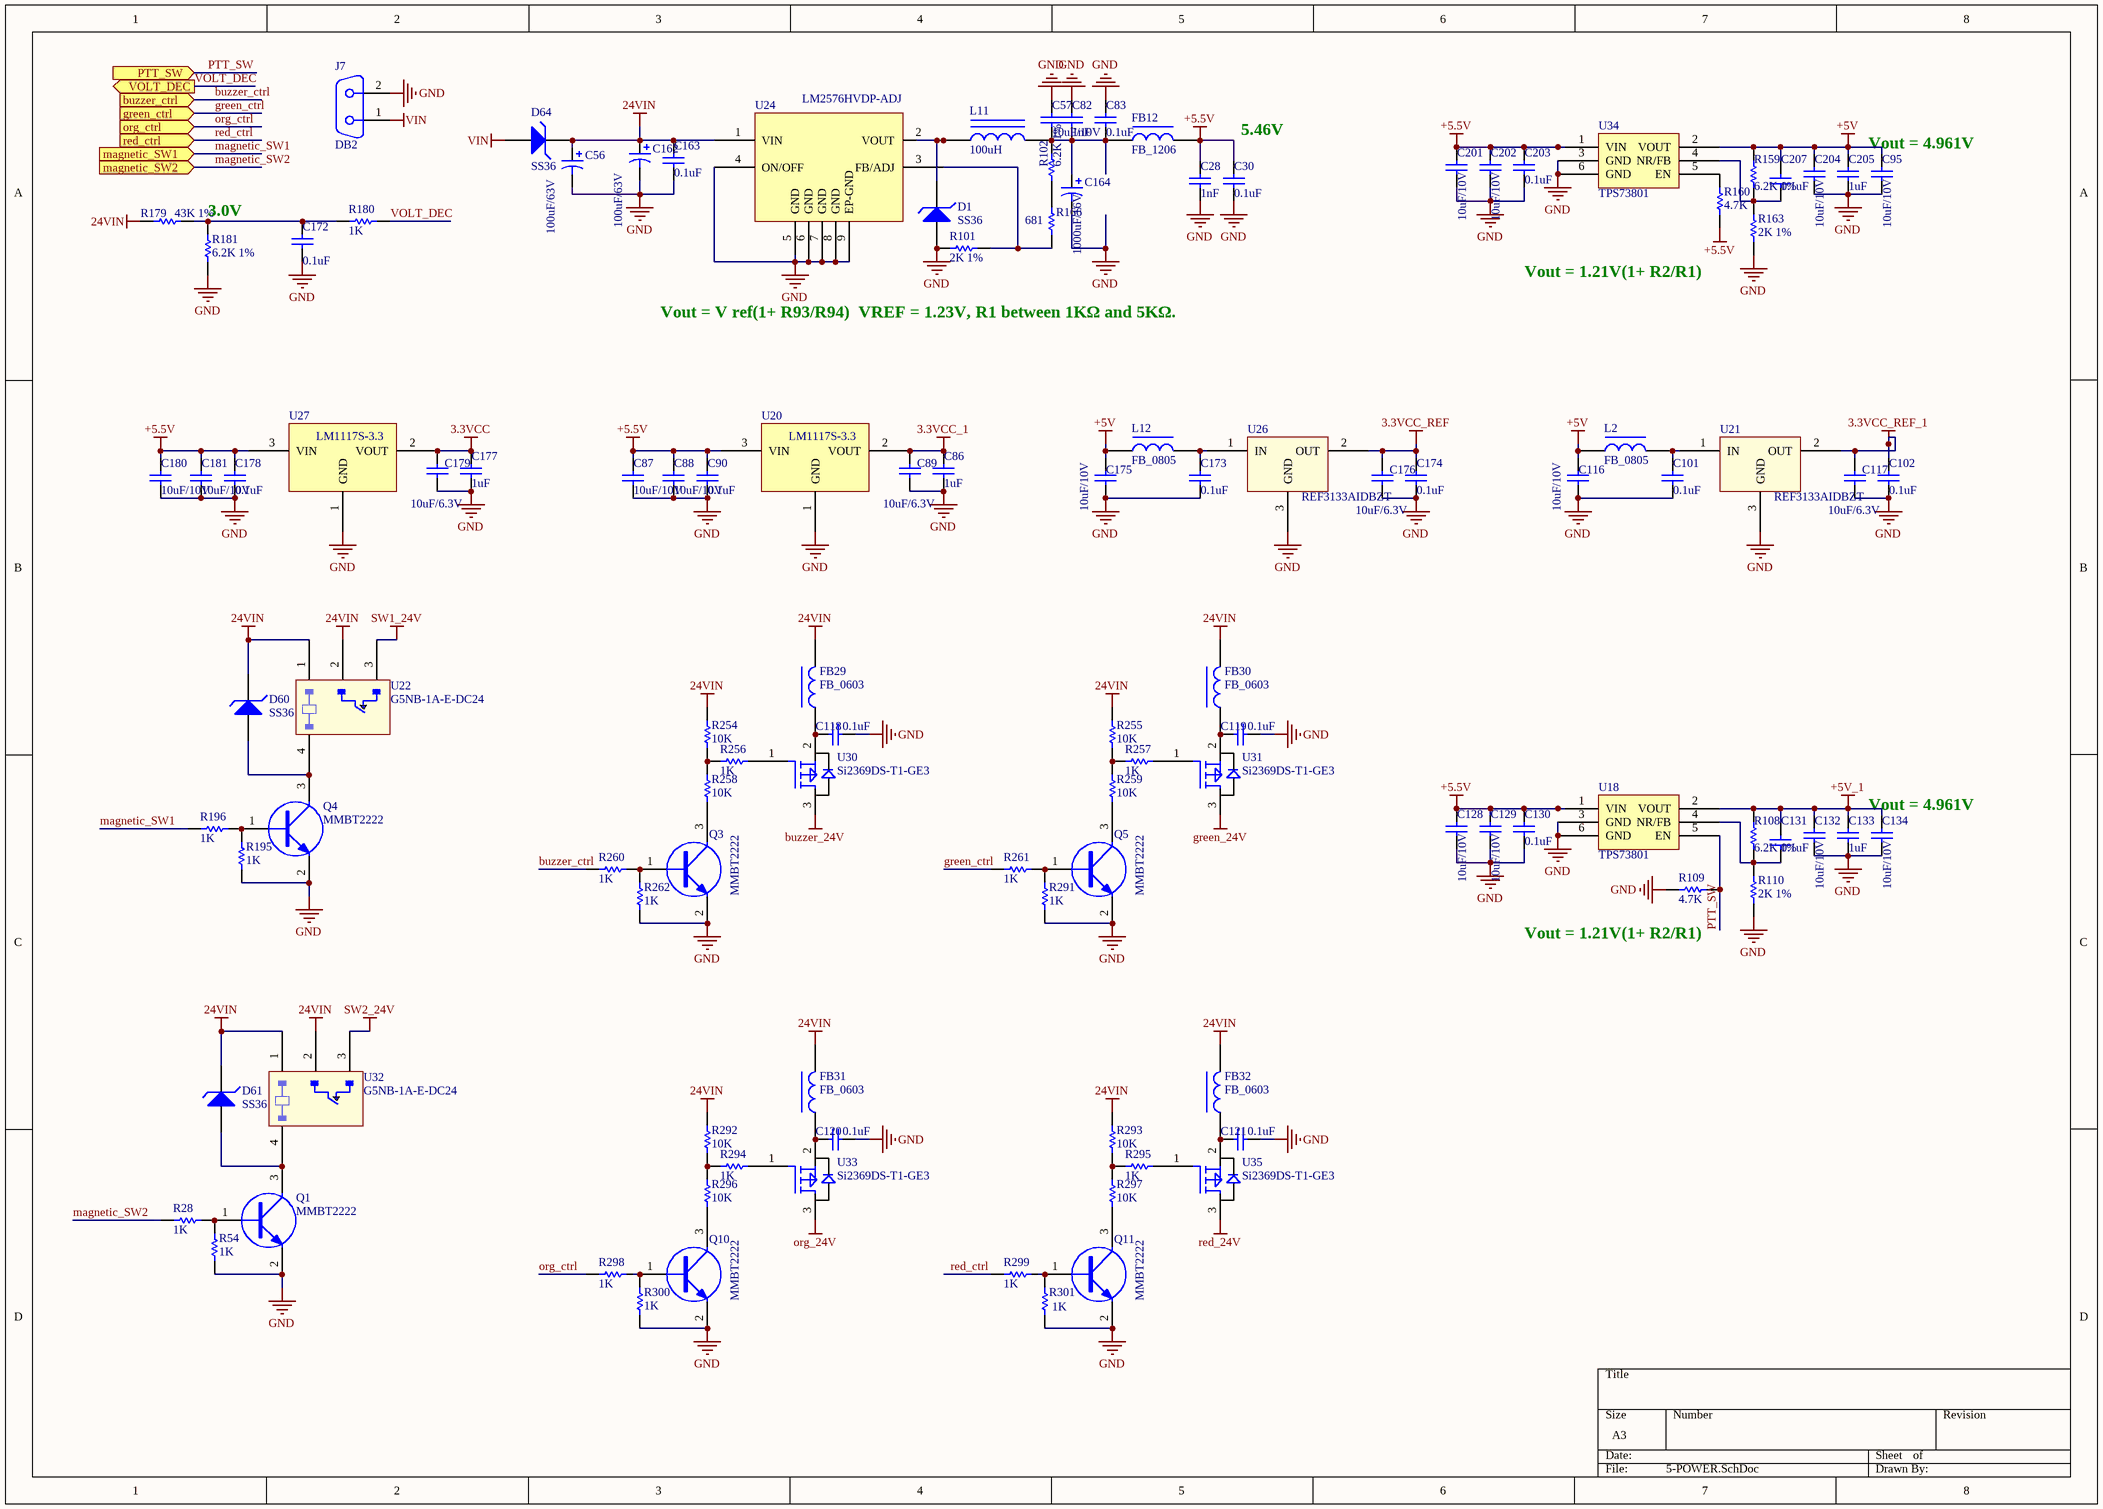
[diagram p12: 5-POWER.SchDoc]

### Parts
C28  1nF  [C0603]
C30  0.1uF  [C0603]
C56  100uF/63V  [ECAP2SM_10R4x10R4]
C57  10uF/10V  [C0805]
C82  1nF  [C0603]
C83  0.1uF  [C0603]
C86  1uF  [C0603]
C87  10uF/10V  [C0805]
C88  10uF/10V  [C0805]
C89  10uF/6.3V  [C0603]
C90  0.1uF  [C0603]
C95  10uF/10V  [C0805]
C101  0.1uF  [C0603]
C102  0.1uF  [C0603]
C116  10uF/10V  [C0805]
C117  10uF/6.3V  [C0603]
C118  0.1uF  [C0603]
C119  0.1uF  [C0603]
C120  0.1uF  [C0603]
C121  0.1uF  [C0603]
C128  10uF/10V  [C0805]
C129  10uF/10V  [C0805]
C130  0.1uF  [C0603]
C131  0.1uF  [C0603]
C132  10uF/10V  [C0805]
C133  1uF  [C0603]
C134  10uF/10V  [C0805]
C162  100uF/63V  [ECAP2SM_10R4x10R4]
C163  0.1uF  [C0603]
C164  1000uF/16V  [ECAP2SM_10R4x10R4]
C172  0.1uF  [C0603]
C173  0.1uF  [C0603]
C174  0.1uF  [C0603]
C175  10uF/10V  [C0805]
C176  10uF/6.3V  [C0603]
C177  1uF  [C0603]
C178  0.1uF  [C0603]
C179  10uF/6.3V  [C0603]
C180  10uF/10V  [C0805]
C181  10uF/10V  [C0805]
C201  10uF/10V  [C0805]
C202  10uF/10V  [C0805]
C203  0.1uF  [C0603]
C204  10uF/10V  [C0805]
C205  1uF  [C0603]
C207  0.1uF  [C0603]
D1  SS36  [DO-214AC]
D60  SS36  [DO-214AC]
D61  SS36  [DO-214AC]
D64  SS36  [DO-214AC]
FB12  FB_1206  [L1206]
FB29  FB_0603  [L0603]
FB30  FB_0603  [L0603]
FB31  FB_0603  [L0603]
FB32  FB_0603  [L0603]
J7  DB2  [DB2TM-VM]  (no BOM)
L2  FB_0805  [L0805]
L11  100uH  [PL2SM-12R5x12R5]
L12  FB_0805  [L0805]
Q1  MMBT2222  [SOT23-3]
Q3  MMBT2222  [SOT23-3]
Q4  MMBT2222  [SOT23-3]
Q5  MMBT2222  [SOT23-3]
Q10  MMBT2222  [SOT23-3]
Q11  MMBT2222  [SOT23-3]
R28  1K  [R0603]
R54  1K  [R0603]
R101  2K 1%  [R0603]
R102  6.2K 1%  [R0603]
R108  6.2K 1%  [R0603]
R109  4.7K  [R0603]
R110  2K 1%  [R0603]
R159  6.2K 1%  [R0603]
R160  4.7K  [R0603]
R163  2K 1%  [R0603]
R166  681  [R0603]
R179  43K 1%  [R0603]
R180  1K  [R0603]
R181  6.2K 1%  [R0603]
R195  1K  [R0603]
R196  1K  [R0603]
R254  10K  [R0603]
R255  10K  [R0603]
R256  1K  [R0603]
R257  1K  [R0603]
R258  10K  [R0603]
R259  10K  [R0603]
R260  1K  [R0603]
R261  1K  [R0603]
R262  1K  [R0603]
R291  1K  [R0603]
R292  10K  [R0603]
R293  10K  [R0603]
R294  1K  [R0603]
R295  1K  [R0603]
R296  10K  [R0603]
R297  10K  [R0603]
R298  1K  [R0603]
R299  1K  [R0603]
R300  1K  [R0603]
R301  1K  [R0603]
U18  TPS73801  [SOT-223-6]
U20  LM1117S-3.3  [SOT-223]
U21  REF3133AIDBZT  [SOT23-3]
U22  G5NB-1A-E-DC24  [G5NB-1A-E-DC24-20R4X7]
U24  LM2576HVDP-ADJ  [SOIC8_1R27_3R9x4R9-1]
U26  REF3133AIDBZT  [SOT23-3]
U27  LM1117S-3.3  [SOT-223]
U30  Si2369DS-T1-GE3  [SOT23-3]
U31  Si2369DS-T1-GE3  [SOT23-3]
U32  G5NB-1A-E-DC24  [G5NB-1A-E-DC24-20R4X7]
U33  Si2369DS-T1-GE3  [SOT23-3]
U34  TPS73801  [SOT-223-6]
U35  Si2369DS-T1-GE3  [SOT23-3]

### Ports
buzzer_ctrl (in), green_ctrl (in), magnetic_SW1 (in), magnetic_SW2 (in), org_ctrl (in), PTT_SW (in), red_ctrl (in), VOLT_DEC (out)

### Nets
3.3VCC: C177.2 C179.2 U27.2(VOUT)
3.3VCC_1: C86.2 C89.2 U20.2(VOUT)
3.3VCC_REF: C174.2 C176.2 U26.2(OUT)
3.3VCC_REF_1: C102.2 C117.2 U21.2(OUT)
24VIN: C56.1 C162.1 C163.2 D60.2(K) D61.2(K) D64.2(K) FB29.2 FB30.2 FB31.2 FB32.2 R179.1 R254.2 R255.2 R292.2 R293.2 U22.1 U22.2 U24.1(VIN) U32.1 U32.2
+5.5V: C28.2 C30.2 C87.2 C88.2 C90.2 C128.2 C129.2 C130.2 C178.2 C180.2 C181.2 C201.2 C202.2 C203.2 FB12.2 R160.2 U18.1(VIN) U20.3(VIN) U27.3(VIN) U34.1(VIN)
+5V: C95.2 C116.2 C175.2 C204.2 C205.2 C207.2 L2.1 L12.1 R159.2 U34.2(VOUT)
+5V_1: C131.2 C132.2 C133.2 C134.2 R108.2 U18.2(VOUT)
buzzer_24V: U30.3(D)
GND: C28.1 C30.1 C56.2 C57.2 C82.2 C83.2 C86.1 C87.1 C88.1 C89.1 C90.1 C95.1 C101.1 C102.1 C116.1 C117.1 C118.1 C119.1 C120.1 C121.1 C128.1 C129.1 C130.1 C132.1 C133.1 C134.1 C162.2 C163.1 C164.2 C172.1 C173.1 C174.1 C175.1 C176.1 C177.1 C178.1 C179.1 C180.1 C181.1 C201.1 C202.1 C203.1 C204.1 C205.1 D1.1(A) J7.2 Q1.2(E) Q3.2(E) Q4.2(E) Q5.2(E) Q10.2(E) Q11.2(E) R54.1 R101.2 R109.1 R110.1 R163.1 R181.1 R195.1 R262.2 R291.2 R300.2 R301.2 U18.3(GND) U18.6(GND) U20.1(GND) U21.3(GND) U24.4(ON/OFF) U24.5(GND) U24.6(GND) U24.7(GND) U24.8(GND) U24.9(EP-GND) U26.3(GND) U27.1(GND) U34.3(GND) U34.6(GND)
green_24V: U31.3(D)
org_24V: U33.3(D)
red_24V: U35.3(D)
SW1_24V: U22.3
SW2_24V: U32.3
VIN: D64.1(A) J7.1
buzzer_ctrl: R260.1 ; port buzzer_ctrl
green_ctrl: R261.1 ; port green_ctrl
magnetic_SW1: R196.1 ; port magnetic_SW1
magnetic_SW2: R28.1 ; port magnetic_SW2
org_ctrl: R298.1 ; port org_ctrl
PTT_SW: R109.2 U18.5(EN) ; port PTT_SW
red_ctrl: R299.1 ; port red_ctrl
VOLT_DEC: R180.1 ; port VOLT_DEC
NetC57_1: C57.1 C82.1 C83.1 C164.1 FB12.1 L11.2 R102.2
NetC101_2: C101.2 L2.2 U21.1(IN)
NetC118_2: C118.2 FB29.1 U30.2(S)
NetC119_2: C119.2 FB30.1 U31.2(S)
NetC120_2: C120.2 FB31.1 U33.2(S)
NetC121_2: C121.2 FB32.1 U35.2(S)
NetC131_1: C131.1 R108.1 R110.2 U18.4(NR/FB)
NetC172_2: C172.2 R179.2 R180.2 R181.2
NetC173_2: C173.2 L12.2 U26.1(IN)
NetC207_1: C207.1 R159.1 R163.2 U34.4(NR/FB)
NetD1_2: D1.2(K) L11.1 U24.2(VOUT)
NetD60_1: D60.1(A) Q4.3(C) U22.4
NetD61_1: D61.1(A) Q1.3(C) U32.4
NetQ1_1: Q1.1(B) R28.2 R54.2
NetQ3_1: Q3.1(B) R260.2 R262.1
NetQ3_3: Q3.3(C) R258.1
NetQ4_1: Q4.1(B) R195.2 R196.2
NetQ5_1: Q5.1(B) R261.2 R291.1
NetQ5_3: Q5.3(C) R259.1
NetQ10_1: Q10.1(B) R298.2 R300.1
NetQ10_3: Q10.3(C) R296.1
NetQ11_1: Q11.1(B) R299.2 R301.1
NetQ11_3: Q11.3(C) R297.1
NetR101_1: R101.1 R166.1 U24.3(FB/ADJ)
NetR102_1: R102.1 R166.2
NetR160_1: R160.1 U34.5(EN)
NetR254_1: R254.1 R256.1 R258.2
NetR255_1: R255.1 R257.1 R259.2
NetR256_2: R256.2 U30.1(G)
NetR257_2: R257.2 U31.1(G)
NetR292_1: R292.1 R294.1 R296.2
NetR293_1: R293.1 R295.1 R297.2
NetR294_2: R294.2 U33.1(G)
NetR295_2: R295.2 U35.1(G)

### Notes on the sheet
- 5.46V
- (near C95) Vout = 4.961V
- (near R181) 3.0V
- Vout = V ref(1+ R93/R94)  VREF = 1.23V, R1 between 1KΩ and 5KΩ.
- Vout = 1.21V(1+ R2/R1)
- (near C134) Vout = 4.961V

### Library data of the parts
C28 C82 = 1000pF贴片电容: as C2010 on sheet 4-RF-PD
C30 C83 C118-C121 = 0.1uF: GRM188R71H104KA01D; MPN: MURATA; WSPN: 01010045
C56 C162 = 100uF/63V电解电容: 电解电容_VEJ101M1JTR-1010_100uF/63V,±20%,表贴10*10; code: 01080002
C57 C87 C88 C95 C116 C128 C129 C132 C134 C175 C180 C181 C201 C202 C204 = 10uF贴片电容: as C2006 on sheet 4-RF-PD
C86 C133 C177 C205 = 1uF贴片电容: 贴片电容_GRM188R61A105KA61D_1uF±10%,10V,0603; code: 01010038
C89 C117 C176 C179 = 10uF贴片电容: as C53 on sheet 3-ADC
C90 C101 C102 C130 C131 C163 C172-C174 C178 C203 C207 = 0.1uF贴片电容: as C25 on sheet 3-ADC
C164 = 1000uF/16V电解电容: 电解电容_VE102M1CTR-1010_1000uF/16V,±20%,表贴10*10; code: 01080003
D1 D60 D61 D64 = 肖特基整流二极管_SS36: 肖特基整流二极管_SS36_封装SMA,3A/60V; code: 01040003
FB12 = 1206贴片磁珠: 贴片磁珠_30R,6A,1206; code: 0103015
FB29-FB32 = 0603贴片磁珠: 贴片磁珠_100R,0603; code: 0103016
J7 = DB2公头座子: 连接器_DB2公头,电源接头; code: 0207001
L2 L12 = 0805贴片磁珠: 贴片磁珠_600R,0805; code: 01030023
L11 = 100uH贴片功率电感: 贴片功率电感_SLF12575T-101M1R9-PF_100uH±20%,额定电流1.9A,12.5x12.5; code: 01030003
Q1 Q3-Q5 Q10 Q11 = MMBT2222: NPN三极管_MMBT2222_表贴SOT23; code: 01050001
R28 R54 R180 R195 R196 R254-R262 R291-R301 = 1K贴片电阻: 贴片电阻_1K±5%,0603; code: 01020082
R101 R110 R163 = 2K贴片电阻: 贴片电阻_2K±5%,0603; code: 01020086
R102 R108 R159 = 6.2K贴片电阻: 贴片电阻_6.2K±5%,0603; code: 01020106
R109 R160 = 4.7K贴片电阻: 贴片电阻_4.7K±5%,0603; code: 01020012
R166 = 1.5K贴片电阻: 0603,681Ω,±1％; code: 01020063
R179 = 12.4K贴片电阻: 贴片电阻_12.4K±1%,0603; code: 01020125
R181 = 1.5K贴片电阻: 贴片电阻_1.5K±5%,0603; code: 01020063
U18 U34 = TPS73701DCQ: LDO_TPS73701DCQ_1A输出,SOT223-6; Maker: TI
U20 U27 = LM1117S-3.3: LDO_LM1117S-3.3_1A输出,SOT223; code: 01060031
U21 U26 = REF3133AIDBZT: LDO_REF3133AIDBZT_3.3V输出,10mA输出,SOT23-3; Maker: TI; code: 01060034
U22 U32 = G5NB-1A-E-DC24: 继电器_G5NB-1A-E-DC24
U24 = LM2576HVDP-ADJ: 稳压集成电路_LM2576HVDP-ADJ_3A输出,SOIC8; code: 03020005; Maker: HTC
U30 U31 U33 U35 = Si2369DS-T1-GE3: P-MOS_Si2369DS-T1-GE3_SOT23; code: 01060087

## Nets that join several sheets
3.3VCC: 1-MCU (108 pins), 3-ADC (36 pins), 5-POWER (C177.2 C179.2 U27.2)
3.3VCC_1: 2-RJ45 (22 pins), 5-POWER (C86.2 C89.2 U20.2)
3.3VCC_REF: 1-MCU (U16.32), 5-POWER (C174.2 C176.2 U26.2)
3.3VCC_REF_1: 3-ADC (U2.21), 5-POWER (C102.2 C117.2 U21.2)
24VIN: 1-MCU (FB1007.1 J3.B2 L1.1 R308.2), 5-POWER (20 pins)
+5V: 1-MCU (19 pins), 3-ADC (FB13.2 FB26.2), 4-RF-PD (33 pins), 5-POWER (10 pins)
+5V_1: 1-MCU (J9.1), 5-POWER (6 pins)
buzzer_24V: 1-MCU (J4.7), 5-POWER (U30.3)
GND: 1-MCU (257 pins), 2-RJ45 (72 pins), 3-ADC (39 pins), 4-RF-PD (57 pins), 5-POWER (77 pins)
green_24V: 1-MCU (J4.2), 5-POWER (U31.3)
org_24V: 1-MCU (J4.6), 5-POWER (U33.3)
red_24V: 1-MCU (J4.1), 5-POWER (U35.3)
SW1_24V: 1-MCU (J4.5), 5-POWER (U22.3)
SW2_24V: 1-MCU (J4.4), 5-POWER (U32.3)
buzzer_ctrl: 1-MCU (R173.2), 5-POWER (R260.1)
green_ctrl: 1-MCU (R106.2), 5-POWER (R261.1)
LINKLED: 1-MCU (R165.1), 2-RJ45 (R78.2 U9.25)
LINKLED2: 1-MCU (R162.2), 2-RJ45 (R280.2 U37.25)
magnetic_SW1: 1-MCU (U16.7), 5-POWER (R196.1)
magnetic_SW2: 1-MCU (U16.8), 5-POWER (R28.1)
org_ctrl: 1-MCU (R223.2), 5-POWER (R298.1)
OUT_OPD: 3-ADC (U10.6), 4-RF-PD (R2001.1 R2058.2)
OUT_RPD: 3-ADC (U17.6), 4-RF-PD (R2022.1 R2059.2)
Port_D0: 1-MCU (R115.2), 3-ADC (U2.15)
Port_D1: 1-MCU (R123.2), 3-ADC (U2.16)
Port_D2: 1-MCU (R142.1), 3-ADC (U2.17)
Port_D3: 1-MCU (R141.1), 3-ADC (U2.18)
Port_D4: 1-MCU (R119.1), 3-ADC (U2.33)
Port_D5: 1-MCU (R113.1), 3-ADC (U2.34)
Port_D6: 1-MCU (R111.1), 3-ADC (U2.63)
Port_D7: 1-MCU (R100.1), 3-ADC (U2.64)
Port_D8: 1-MCU (R98.1), 3-ADC (U2.65)
Port_D9: 1-MCU (R95.1), 3-ADC (U2.66)
Port_D10: 1-MCU (R94.1), 3-ADC (U2.78)
Port_D11: 1-MCU (R59.1), 3-ADC (U2.79)
Port_D12: 1-MCU (R47.1), 3-ADC (U2.80)
Port_D13: 1-MCU (R27.1), 3-ADC (U2.7)
Port_D14: 1-MCU (R26.1), 3-ADC (U2.8)
Port_D15: 1-MCU (R20.1), 3-ADC (U2.9)
PTT_SW: 1-MCU (R176.2), 5-POWER (R109.2 U18.5)
red_ctrl: 1-MCU (R208.2), 5-POWER (R299.1)
SPI1_MISO: 1-MCU (R328.1), 2-RJ45 (U37.34)
SPI1_MOSI: 1-MCU (R329.1), 2-RJ45 (U37.35)
SPI1_NSS: 1-MCU (R327.1), 2-RJ45 (R271.1 U37.32)
SPI1_SCK: 1-MCU (R326.1), 2-RJ45 (U37.33)
SPI2_MISO: 1-MCU (R30.2), 2-RJ45 (U9.34)
SPI2_MOSI: 1-MCU (R29.2), 2-RJ45 (U9.35)
SPI2_NSS: 1-MCU (R35.2), 2-RJ45 (R69.1 U9.32)
SPI2_SCK: 1-MCU (R32.2), 2-RJ45 (U9.33)
VENV2-: 1-MCU (U16.22), 4-RF-PD (C2037.2 C2038.2 R2044.1)
VENV+: 1-MCU (U16.29), 4-RF-PD (C2012.2 C2014.2 R2007.1 R2058.1)
VENV-: 1-MCU (U16.27), 4-RF-PD (C2023.2 C2024.2 R2024.1 R2059.1)
VOLT_DEC: 1-MCU (U16.43), 5-POWER (R180.1)
VRMS2-: 1-MCU (U16.18), 4-RF-PD (C2041.2 C2042.2 R2040.2 R2048.2)
VRMS+: 1-MCU (U16.28), 4-RF-PD (C2011.2 C2013.2 R2001.2 R2008.2)
VRMS-: 1-MCU (U16.26), 4-RF-PD (C2027.2 C2028.2 R2022.2 R2030.2)
W5500_INTn: 1-MCU (U16.60), 2-RJ45 (U9.36)
W5500_INTn1: 1-MCU (U16.70), 2-RJ45 (U37.36)
W5500_RSTn: 1-MCU (U16.59), 2-RJ45 (R67.1 U9.37)
W5500_RSTn1: 1-MCU (U16.69), 2-RJ45 (R269.1 U37.37)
